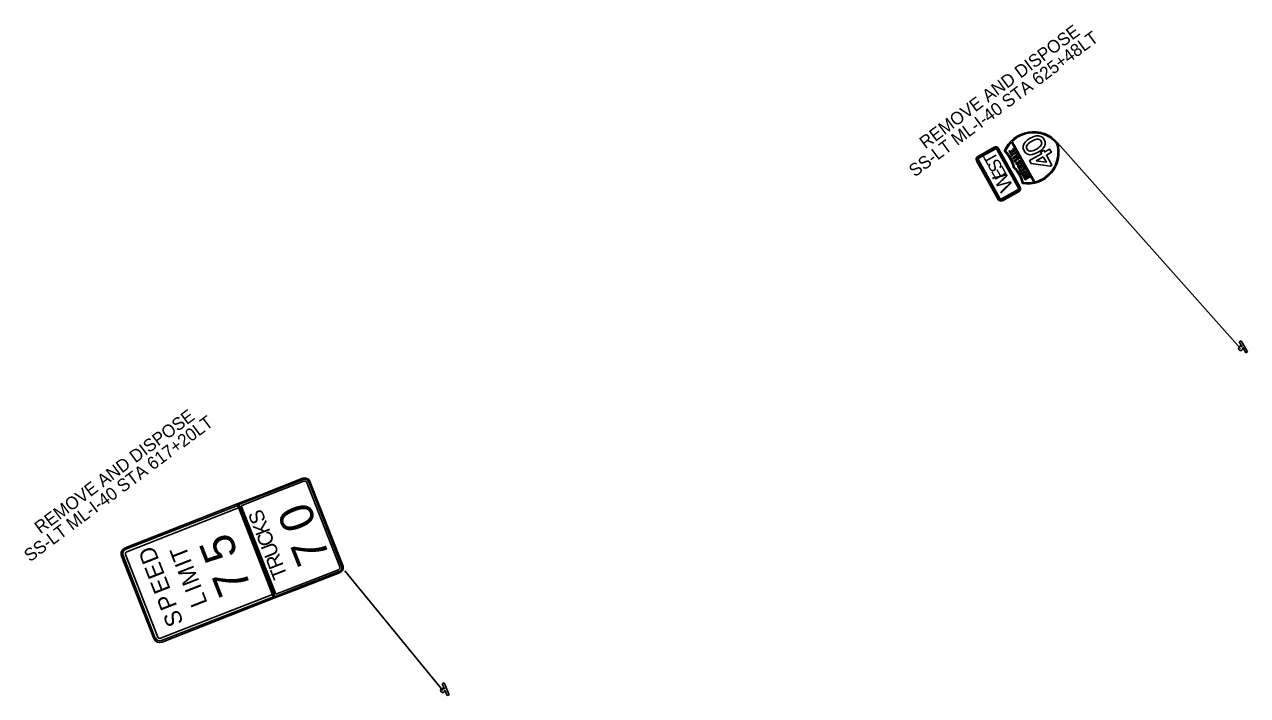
# Model space of a CAD drawing. Extents: x 641128 to 649424, y 422807 to 432853.
# Drawn here: x 641883 to 643042, y 424388 to 425023 of the extents above; entities that cross this region are included whole.
import ezdxf

# ---------------------------------------------------------------- set-up
doc = ezdxf.new("R2010")
doc.units = 0
for name, color, linetype in [('R_Anno_Text', 7, 'Continuous'), ('R_Dimension', 7, 'Continuous'), ('S_SIGN', 7, 'Continuous')]:
    doc.layers.add(name, color=color, linetype=linetype)

msp = doc.modelspace()

# ---------------------------------------------------------------- linework, layer by layer
at = {"layer": 'S_SIGN'}
for p, q in [((642818.3, 424911.8), (642839.5, 424873.9)), ((642840.5, 424874.1), (642819, 424912.5)), ((642862, 424911.4), (643035.7, 424716.5)), ((642802.1, 424907.1), (642786.4, 424898.3)), ((642826.7, 424869.3), (642806.2, 424906)), ((642785.3, 424894.2), (642805.8, 424857.6)), ((642809.9, 424856.4), (642825.6, 424865.2)), ((643034.4, 424722.7), (643036.2, 424723.7)), ((643036.2, 424723.7), (643042.2, 424713.4)), ((643037.2, 424717.9), (643034.4, 424722.7)), ((643037.2, 424717.9), (643037.2, 424717.9)), ((643037.7, 424717.2), (643037.6, 424717.1)), ((643040.5, 424712.4), (643037.7, 424717.2)), ((643042.2, 424713.4), (643040.5, 424712.4)), ((642186.3, 424505.9), (642279.2, 424392.4)), ((642278.8, 424398.7), (642280.7, 424399.5)), ((642280.9, 424393.6), (642278.8, 424398.7)), ((642280.7, 424399.5), (642285.2, 424388.4)), ((642280.8, 424393.6), (642280.9, 424393.6)), ((642283.3, 424387.6), (642281.2, 424392.8)), ((642281.2, 424392.8), (642281.2, 424392.8)), ((642285.2, 424388.4), (642283.3, 424387.6))]:
    msp.add_line(p, q, dxfattribs=at)
for points in [[(642836.1, 424915.7), (642833.5, 424914), (642831.3, 424912), (642830, 424910.1), (642829.4, 424908), (642829.5, 424905.8), (642830.3, 424903.6), (642831.7, 424901.9), (642833.5, 424900.6), (642835.7, 424900), (642837.9, 424900.1), (642840.8, 424901), (642843.6, 424902.3), (642846.2, 424904), (642848.5, 424906.1), (642849.7, 424907.9), (642850.4, 424910), (642850.3, 424912.3), (642849.5, 424914.4), (642848.1, 424916.2), (642846.3, 424917.4), (642844.1, 424918), (642841.9, 424917.9), (642839, 424917.1), (642836.1, 424915.7)], [(642831.7, 424901.9), (642833.5, 424900.6), (642835.7, 424900), (642837.9, 424900.1), (642840.8, 424901), (642843.6, 424902.3), (642846.2, 424904), (642848.5, 424906.1), (642849.7, 424907.9), (642850.4, 424910), (642850.3, 424912.3), (642849.5, 424914.4), (642848.1, 424916.2), (642846.3, 424917.4), (642844.1, 424918), (642841.9, 424917.9), (642839, 424917.1), (642836.1, 424915.7), (642833.5, 424914), (642831.3, 424912), (642830, 424910.1), (642829.4, 424908), (642829.5, 424905.8), (642830.3, 424903.6), (642831.7, 424901.9)], [(642837.8, 424912.8), (642840.2, 424914), (642842.6, 424914.7), (642843.8, 424914.7), (642844.9, 424914.4), (642845.9, 424913.7), (642846.6, 424912.8), (642847, 424911.8), (642847.1, 424910.9), (642846.9, 424909.9), (642846.5, 424909), (642845.8, 424908), (642844.8, 424907.1), (642843.6, 424906.2), (642842, 424905.2), (642839.6, 424904.1), (642837.2, 424903.4), (642836, 424903.3), (642834.9, 424903.7), (642833.9, 424904.3), (642833.2, 424905.3), (642832.8, 424906.2), (642832.7, 424907.2), (642832.8, 424908.1), (642833.3, 424909.1), (642834, 424910), (642835, 424911), (642836.2, 424911.9), (642837.8, 424912.8)], [(642837.8, 424912.8), (642840.2, 424914), (642842.6, 424914.7), (642843.8, 424914.7), (642844.9, 424914.4), (642845.9, 424913.7), (642846.6, 424912.8), (642847, 424911.8), (642847.1, 424910.9), (642846.9, 424909.9), (642846.5, 424909), (642845.8, 424908), (642844.8, 424907.1), (642843.6, 424906.2), (642842, 424905.2), (642839.6, 424904.1), (642837.2, 424903.4), (642836, 424903.3), (642834.9, 424903.7), (642833.9, 424904.3), (642833.2, 424905.3), (642832.8, 424906.2), (642832.7, 424907.2), (642832.8, 424908.1), (642833.3, 424909.1), (642834, 424910), (642835, 424911), (642836.2, 424911.9), (642837.8, 424912.8)], [(642802.5, 424906.5), (642786.8, 424897.7)], [(642787.4, 424896.6), (642803.1, 424905.4)], [(642802.5, 424906.5), (642802.5, 424906.5), (642802.5, 424906.5)], [(642804.5, 424905), (642825, 424868.3)], [(642826.1, 424868.9), (642805.6, 424905.6)], [(642820.4, 424906), (642821.6, 424903.8), (642817.2, 424901.4), (642816.1, 424903.5), (642816.7, 424903.8), (642817.5, 424902.3), (642818.6, 424902.9), (642818.1, 424903.8), (642818.7, 424904.2), (642819.2, 424903.3), (642820.7, 424904.1), (642819.8, 424905.6), (642820.4, 424906)], [(642818.2, 424900.9), (642818.7, 424900.2), (642822.5, 424902.3), (642822.8, 424901.7), (642819, 424899.5), (642819.5, 424898.8), (642818.9, 424898.4), (642817.7, 424900.6), (642818.2, 424900.9)], [(642823.4, 424900.6), (642823.7, 424900), (642822.7, 424899), (642823.2, 424898.2), (642824.6, 424898.5), (642824.9, 424897.9), (642819.9, 424896.5), (642819.6, 424897.1), (642823.4, 424900.6)], [(642822.2, 424898.5), (642821.1, 424897.6), (642822.5, 424898), (642822.2, 424898.5)], [(642849, 424904.2), (642846.1, 424902.6), (642847, 424900.9), (642835.4, 424894.5), (642837.1, 424891.6), (642855, 424889.2), (642856.8, 424890.2), (642851.5, 424899.7), (642856.3, 424902.3), (642854.6, 424905.2), (642849.9, 424902.6), (642849, 424904.2)], [(642835.4, 424894.5), (642837.1, 424891.6), (642855, 424889.2), (642856.8, 424890.2), (642851.5, 424899.7), (642856.3, 424902.3), (642854.6, 424905.2), (642849.9, 424902.6), (642849, 424904.2), (642846.1, 424902.6), (642847, 424900.9), (642835.4, 424894.5)], [(642848.6, 424898), (642851.5, 424893), (642841.9, 424894.3), (642848.6, 424898)], [(642848.6, 424898), (642851.5, 424893), (642841.9, 424894.3), (642848.6, 424898)], [(642785.9, 424894.6), (642806.4, 424858)], [(642785.9, 424894.6), (642785.9, 424894.6), (642785.9, 424894.6)], [(642807.5, 424858.6), (642787, 424895.2)], [(642821.3, 424895.5), (642821.7, 424894.8), (642825.5, 424896.9), (642825.8, 424896.3), (642822, 424894.1), (642822.5, 424893.4), (642821.9, 424893), (642820.7, 424895.2), (642821.3, 424895.5)], [(642826.7, 424891.6), (642826.4, 424892.2), (642826.5, 424892.3), (642826.6, 424892.4), (642826.7, 424892.5), (642826.8, 424892.5), (642826.8, 424892.6), (642826.9, 424892.7), (642826.9, 424892.8), (642826.9, 424892.9), (642826.9, 424893), (642826.8, 424893.1), (642826.8, 424893.2), (642826.7, 424893.3), (642826.7, 424893.4), (642826.6, 424893.5), (642826.5, 424893.5), (642826.4, 424893.6), (642826.3, 424893.6), (642826.2, 424893.6), (642826.1, 424893.6), (642826, 424893.5), (642825.9, 424893.5), (642825.8, 424893.5), (642825.8, 424893.4), (642825.7, 424893.4), (642825.6, 424893.3), (642825.6, 424893.3), (642825.5, 424893.2), (642825.5, 424893.2), (642825.4, 424893.1), (642825.4, 424893), (642825.4, 424893), (642825.3, 424892.9), (642825.3, 424892.8), (642825.3, 424892.8), (642825.3, 424892.7), (642825.2, 424892.6), (642825.2, 424892.5), (642825.2, 424892.5), (642825.2, 424892.4), (642825.2, 424891.7), (642825.2, 424891.7), (642825.2, 424891.6), (642825.2, 424891.5), (642825.2, 424891.4), (642825.1, 424891.4), (642825.1, 424891.3), (642825.1, 424891.2), (642825, 424891.2), (642825, 424891.1), (642825, 424891), (642824.9, 424891), (642824.9, 424890.9), (642824.8, 424890.9), (642824.8, 424890.8), (642824.7, 424890.8), (642824.6, 424890.7), (642824.6, 424890.7), (642824.5, 424890.6), (642824.4, 424890.6), (642824.2, 424890.6), (642824.1, 424890.5), (642824, 424890.5), (642823.9, 424890.5), (642823.8, 424890.5), (642823.7, 424890.5), (642823.6, 424890.6), (642823.5, 424890.6), (642823.4, 424890.7), (642823.3, 424890.7), (642823.2, 424890.8), (642823.1, 424890.8), (642823.1, 424890.9), (642823, 424891), (642822.9, 424891.1), (642822.9, 424891.2), (642822.8, 424891.3), (642822.8, 424891.4), (642822.7, 424891.5), (642822.7, 424891.6), (642822.7, 424891.7), (642822.7, 424891.8), (642822.7, 424891.9), (642822.7, 424892), (642822.7, 424892.1), (642822.8, 424892.2), (642822.8, 424892.3), (642822.9, 424892.4), (642822.9, 424892.5), (642823, 424892.6), (642823.1, 424892.7), (642823.1, 424892.7), (642823.2, 424892.8), (642823.3, 424892.9), (642823.7, 424892.3), (642823.6, 424892.2), (642823.5, 424892.1), (642823.5, 424892), (642823.4, 424891.9)], [(642823.4, 424891.9), (642823.4, 424891.8), (642823.4, 424891.7), (642823.4, 424891.6), (642823.5, 424891.5), (642823.5, 424891.4), (642823.6, 424891.3), (642823.7, 424891.3), (642823.8, 424891.2), (642823.9, 424891.2), (642824, 424891.2), (642824.1, 424891.3), (642824.2, 424891.3), (642824.3, 424891.3), (642824.3, 424891.4), (642824.4, 424891.5), (642824.4, 424891.5), (642824.5, 424891.6), (642824.5, 424891.7), (642824.5, 424891.8), (642824.5, 424892.4), (642824.5, 424892.6), (642824.6, 424892.7), (642824.6, 424892.9), (642824.6, 424893.1), (642824.7, 424893.2), (642824.8, 424893.4), (642824.9, 424893.5), (642825, 424893.6), (642825.1, 424893.7), (642825.2, 424893.8), (642825.3, 424893.9), (642825.4, 424894), (642825.5, 424894.1), (642825.6, 424894.2), (642825.7, 424894.2), (642825.8, 424894.2), (642826, 424894.3), (642826.1, 424894.3), (642826.2, 424894.3), (642826.3, 424894.3), (642826.4, 424894.3), (642826.5, 424894.3), (642826.6, 424894.2), (642826.7, 424894.2), (642826.8, 424894.2), (642826.9, 424894.1), (642827, 424894.1), (642827.1, 424894), (642827.1, 424893.9), (642827.2, 424893.8), (642827.3, 424893.8), (642827.4, 424893.7), (642827.4, 424893.6), (642827.5, 424893.5), (642827.5, 424893.4), (642827.5, 424893.3), (642827.6, 424893.2), (642827.6, 424893.1), (642827.6, 424893), (642827.6, 424892.9), (642827.6, 424892.8), (642827.6, 424892.7), (642827.5, 424892.5), (642827.5, 424892.4), (642827.5, 424892.3), (642827.4, 424892.2), (642827.4, 424892.1), (642827.3, 424892.1), (642827.2, 424892), (642827.2, 424891.9), (642827.1, 424891.8), (642827, 424891.8), (642826.9, 424891.7), (642826.7, 424891.6)], [(642828.4, 424891.6), (642828.8, 424891), (642827.1, 424889.2), (642827.4, 424888.7), (642829.4, 424889.8), (642829.8, 424889.2), (642825.4, 424886.8), (642824.6, 424888.1), (642824.6, 424888.3), (642824.5, 424888.4), (642824.5, 424888.5), (642824.5, 424888.6), (642824.5, 424888.8), (642824.5, 424888.9), (642824.5, 424889), (642824.6, 424889.1), (642824.6, 424889.3), (642824.7, 424889.4), (642824.8, 424889.5), (642824.8, 424889.6), (642825, 424889.7), (642825.2, 424889.8), (642825.4, 424889.9), (642825.6, 424890), (642825.7, 424890), (642825.8, 424890), (642825.9, 424890), (642826, 424890), (642826.1, 424890), (642826.2, 424890), (642826.3, 424890), (642826.4, 424890), (642826.5, 424889.9), (642826.5, 424889.9), (642826.6, 424889.8), (642828.4, 424891.6)], [(642826.8, 424888.4), (642826.3, 424889.1), (642826.3, 424889.2), (642826.1, 424889.3), (642826, 424889.3), (642825.8, 424889.3), (642825.7, 424889.3), (642825.6, 424889.2), (642825.4, 424889.1), (642825.3, 424889), (642825.3, 424889), (642825.2, 424888.9), (642825.2, 424888.9), (642825.2, 424888.8), (642825.2, 424888.8), (642825.2, 424888.7), (642825.2, 424888.7), (642825.2, 424888.6), (642825.2, 424888.5), (642825.2, 424888.5), (642825.7, 424887.7), (642826.8, 424888.4)], [(642830.2, 424888.5), (642831.4, 424886.3), (642827, 424883.9), (642825.8, 424886), (642826.5, 424886.3), (642827.3, 424884.8), (642828.4, 424885.4), (642827.9, 424886.4), (642828.5, 424886.7), (642829, 424885.8), (642830.4, 424886.6), (642829.6, 424888.1), (642830.2, 424888.5)], [(642828, 424883.5), (642828.5, 424882.7), (642832.2, 424884.8), (642832.6, 424884.2), (642828.8, 424882.1), (642829.2, 424881.3), (642828.6, 424881), (642827.4, 424883.1), (642828, 424883.5)], [(642833.4, 424882.7), (642833.7, 424882.2), (642831.5, 424879.3), (642834.4, 424880.9), (642834.8, 424880.3), (642830.4, 424877.8), (642830.1, 424878.4), (642832, 424881), (642829.4, 424879.6), (642829.1, 424880.2), (642833.4, 424882.7)], [(642835.3, 424879.3), (642835.6, 424878.7), (642831.3, 424876.3), (642830.9, 424876.9), (642835.3, 424879.3)], [(642824.6, 424867), (642808.9, 424858.2)], [(642809.5, 424857.1), (642825.2, 424865.9)], [(642826.1, 424868.9), (642826.1, 424868.9), (642826.1, 424868.9)], [(642809.5, 424857.1), (642809.5, 424857.1), (642809.5, 424857.1)], [(642146.4, 424593.4), (642106.6, 424577.8)], [(642107, 424576.7), (642146.8, 424592.3)], [(642147.5, 424590.6), (642107.7, 424575.1)], [(642147.5, 424590.6), (642147.5, 424590.6), (642147.5, 424590.6)], [(642181.6, 424509.7), (642150.4, 424589.3)], [(642152.1, 424590), (642183.3, 424510.4)], [(642184.4, 424510.8), (642153.2, 424590.4)], [(642106.6, 424577.8), (642084.3, 424569.1), (642119.2, 424479.7), (642141.6, 424488.4), (642141.6, 424488.4), (642141.6, 424488.4)], [(642087.5, 424569.1), (642107, 424576.7)], [(642107.7, 424575.1), (642088.1, 424567.4)], [(642107.7, 424575.1), (642107.7, 424575.1), (642107.7, 424575.1)], [(642084.3, 424569.1), (641978.1, 424527.6)], [(641978.6, 424526.2), (642084.8, 424567.7)], [(642085.7, 424565.4), (641979.6, 424523.8)], [(642085.7, 424565.4), (642085.7, 424565.4), (642085.7, 424565.4)], [(642086.5, 424566.7), (642085.8, 424568.4), (642087.5, 424569.1), (642087.5, 424569.1), (642087.5, 424569.1)], [(642119.3, 424482.9), (642086.5, 424566.7)], [(642088.1, 424567.4), (642120.9, 424483.6)], [(642088.1, 424567.4), (642088.1, 424567.4), (642088.1, 424567.4)], [(641974.7, 424519.8), (642005.3, 424441.6)], [(642006.7, 424442.1), (641976.1, 424520.3)], [(641978.4, 424521.3), (642009, 424443)], [(641978.4, 424521.3), (641978.4, 424521.3), (641978.4, 424521.3)], [(642140.5, 424491.2), (642180.3, 424506.8)], [(642180.9, 424505.1), (642141.1, 424489.6)], [(642141.6, 424488.4), (642181.4, 424504)], [(642181.6, 424509.7), (642181.6, 424509.7), (642181.6, 424509.7)], [(642184.4, 424510.8), (642184.4, 424510.8), (642184.4, 424510.8)], [(642011.6, 424441.9), (642117.8, 424483.4)], [(642118.7, 424481.1), (642012.5, 424439.6)], [(642121.6, 424481.9), (642119.9, 424481.3), (642119.3, 424482.9), (642119.3, 424482.9), (642119.3, 424482.9)], [(642120.9, 424483.6), (642140.5, 424491.2)], [(642120.9, 424483.6), (642120.9, 424483.6), (642120.9, 424483.6)], [(642141.1, 424489.6), (642121.6, 424481.9)], [(642140.5, 424491.2), (642140.5, 424491.2), (642140.5, 424491.2)], [(642013.1, 424438.2), (642119.2, 424479.7), (642119.2, 424479.7), (642119.2, 424479.7)], [(642011.6, 424441.9), (642011.6, 424441.9), (642011.6, 424441.9)]]:
    msp.add_lwpolyline(points, dxfattribs=at)
for centre, radius, start, end in [((642839.3, 424891.8), 30, 40.7506, 157.5446), ((642839.3, 424891.8), 29, 41.1431, 134.4601), ((642839.3, 424891.8), 29, 136.4767, 156.2176), ((642833.5, 424902.3), 30, 260.8824, 17.6764), ((642833.5, 424902.3), 29, 283.9669, 17.284), ((642787.9, 424895.7), 3, 119.2135, 209.2137), ((642787.9, 424895.7), 2.25, 119.2135, 209.2137), ((642803.6, 424904.5), 3, 29.2135, 119.2137), ((642803.6, 424904.5), 2.25, 29.2135, 119.2137), ((642803.6, 424904.5), 1, 29.2135, 119.2137), ((642790.8, 424881.6), 30, 12.2225, 46.2046), ((642790.8, 424881.7), 31, 12.639, 44.7745), ((642787.9, 424895.7), 1, 119.2135, 209.2137), ((642799.4, 424866.3), 30, 12.2225, 46.2046), ((642799.4, 424866.2), 31, 13.6526, 45.788), ((642824.1, 424867.8), 1, 299.2133, 29.2135), ((642824.1, 424867.8), 2.25, 299.2133, 29.2135), ((642824.1, 424867.8), 3, 299.2133, 29.2135), ((642833.5, 424902.3), 29, 262.2094, 281.9501), ((642808.4, 424859.1), 3, 209.2137, 299.2133), ((642808.4, 424859.1), 2.25, 209.2137, 299.2133), ((642808.4, 424859.1), 1, 209.2137, 299.2133), ((643035.7, 424716.5), 2, 120.2285, 17.9086), ((643035.7, 424716.5), 2, 44.0906, 120.2285), ((642148.3, 424588.5), 5.26, 21.366, 111.3662), ((642148.3, 424588.5), 4.06, 21.366, 111.3662), ((642148.3, 424588.5), 2.26, 21.366, 111.3662), ((641980.3, 424522), 6, 111.3659, 201.3661), ((641980.3, 424522), 4.5, 111.3659, 201.3661), ((641980.3, 424522), 2, 111.3659, 201.3661), ((642179.5, 424508.9), 2.26, 291.3657, 21.366), ((642179.5, 424508.9), 4.06, 291.3657, 21.366), ((642179.5, 424508.9), 5.26, 291.3657, 21.366), ((642010.9, 424443.8), 6, 201.3661, 291.3657), ((642010.9, 424443.8), 4.5, 201.3661, 291.3657), ((642010.9, 424443.8), 2, 201.3661, 291.3657), ((642279.2, 424392.4), 2, 111.9221, 9.6022), ((642279.2, 424392.4), 2, 35.7842, 111.9221)]:
    msp.add_arc(centre, radius, start, end, dxfattribs=at)

# ---------------------------------------------------------------- texts
at = {"layer": 'R_Anno_Text'}
for s, p in [('REMOVE AND DISPOSE', (641897.8, 424540.3)), ('SS-LT ML-I-40 STA 617+20LT', (641887.9, 424513.7))]:
    msp.add_text(s, height=12, rotation=36.704, dxfattribs=at).set_placement(p)
at = {"layer": 'R_Dimension'}
for s, p in [('SS-LT ML-I-40 STA 625+48LT', (642726.8, 424878.4)), ('REMOVE AND DISPOSE', (642736.8, 424905))]:
    msp.add_text(s, height=12, rotation=36.5549, dxfattribs=at).set_placement(p)
at = {"layer": 'S_SIGN'}
for s, height, rotation, p in [('T', 12, 119.2135, (642806.4, 424895.4)), ('S', 12, 119.2135, (642810.6, 424887.9)), ('E', 12, 119.2135, (642814.5, 424880.9)), ('W', 14, 119.2135, (642820.7, 424869.8)), ('S', 14, 111.3659, (642111.8, 424553.5)), ('0', 32, 111.3659, (642160.1, 424550.8)), ('K', 14, 111.3659, (642116, 424542.9)), ('5', 32, 111.3659, (642085.6, 424521.6)), ('C', 14, 111.3659, (642120.1, 424532.4)), ('D', 16, 111.3659, (642010.5, 424516.1)), ('U', 14, 111.3659, (642124.3, 424521.6)), ('7', 32, 111.3659, (642172.6, 424519)), ('T', 16, 111.3659, (642039.5, 424518.9)), ('I', 16, 111.3659, (642041.7, 424513.3)), ('R', 14, 111.3659, (642128.6, 424510.8)), ('E', 16, 111.3659, (642016, 424502.1)), ('M', 16, 111.3659, (642048.6, 424495.7)), ('T', 14, 111.3659, (642132.3, 424501.1)), ('E', 16, 111.3659, (642021.5, 424488.1)), ('I', 16, 111.3659, (642051.1, 424489.3)), ('7', 32, 111.3659, (642098.1, 424489.9)), ('P', 16, 111.3659, (642027.6, 424472.4)), ('L', 16, 111.3659, (642056.5, 424475.3)), ('S', 16, 111.3659, (642033.7, 424456.7))]:
    msp.add_text(s, height=height, rotation=rotation, dxfattribs=at).set_placement(p)

doc.saveas('drawing.dxf')
